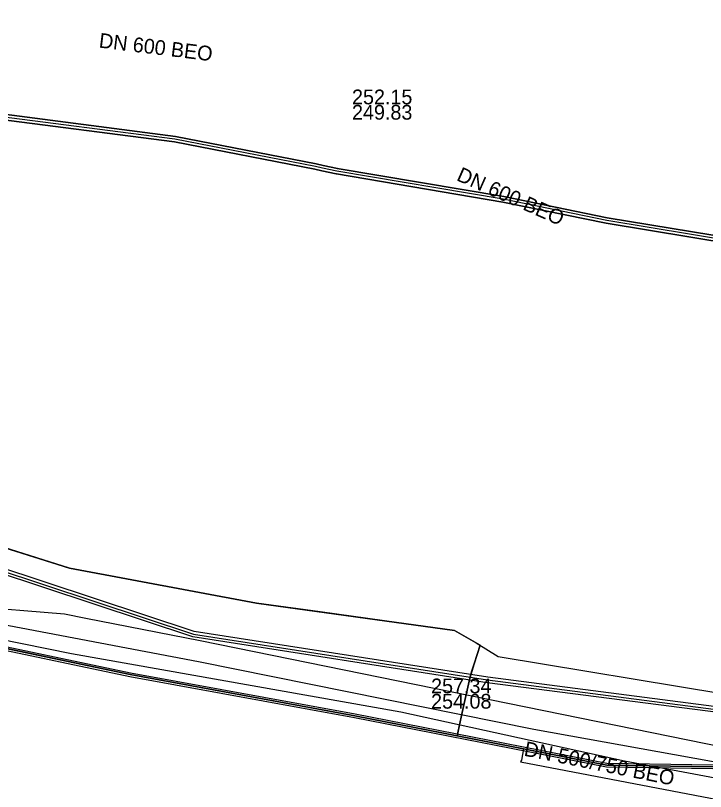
# Model space of a CAD drawing. Extents: x -599951 to -598963, y -1164095 to -1162939.
# Drawn here: x -599781.05 to -599743.65, y -1163060.04 to -1163017.95 of the extents above; entities that cross this region are included whole.
import ezdxf

# ---------------------------------------------------------------- set-up
doc = ezdxf.new("R2010")
doc.units = 0
for name, color, linetype in [('Vrstva 12', 7, 'Continuous'), ('Vrstva 20', 7, 'Continuous'), ('Vrstva 42', 7, 'Continuous'), ('Vrstva 44', 7, 'Continuous'), ('Vrstva 50', 7, 'Continuous'), ('Vrstva 55', 7, 'Continuous'), ('Vrstva 58', 7, 'Continuous')]:
    doc.layers.add(name, color=color, linetype=linetype)

msp = doc.modelspace()

# ---------------------------------------------------------------- linework, layer by layer
at = {"layer": 'Vrstva 12'}
for p, q in [((-599777.23, -1163050.66), (-599778.4, -1163050.43)), ((-599771.04, -1163051.87), (-599777.23, -1163050.66)), ((-599687.5, -1163068.9), (-599771.04, -1163051.87))]:
    msp.add_line(p, q, dxfattribs=at)
msp.add_lwpolyline([(-599778.4, -1163050.43), (-599783.7, -1163049.99), (-599784.71, -1163049.77)], dxfattribs=at)
at = {"layer": 'Vrstva 20'}
msp.add_lwpolyline([(-599883.05, -1163052.54), (-599873.56, -1163051.94), (-599873.14, -1163051.47), (-599872.98, -1163049.36), (-599872.6, -1163047.57), (-599869.57, -1163036.17), (-599869.08, -1163035.73), (-599867.99, -1163036.09), (-599863.42, -1163036.97), (-599853.5, -1163038.54), (-599849.37, -1163039.34), (-599847.49, -1163039.61), (-599846.18, -1163040.18), (-599841.31, -1163041.11), (-599828.6, -1163043.61), (-599815.43, -1163046.17), (-599809.1, -1163047.15), (-599803.22, -1163048.59), (-599792.42, -1163050.98), (-599783.94, -1163051.78), (-599774.84, -1163053.7), (-599762.66, -1163055.93), (-599749, -1163058.61), (-599740.93, -1163058.73)], dxfattribs=at)
at = {"layer": 'Vrstva 42'}
for p, q in [((-599783.799, -1163046.138), (-599778.116, -1163047.934)), ((-599783.799, -1163046.138), (-599778.116, -1163047.934)), ((-599778.116, -1163047.934), (-599767.984, -1163049.822)), ((-599778.116, -1163047.934), (-599767.984, -1163049.822)), ((-599767.984, -1163049.822), (-599757.25, -1163051.301)), ((-599767.984, -1163049.822), (-599757.25, -1163051.301)), ((-599757.25, -1163051.301), (-599756.084, -1163051.968)), ((-599757.25, -1163051.301), (-599756.084, -1163051.968)), ((-599756.084, -1163051.968), (-599754.889, -1163052.719)), ((-599756.084, -1163051.968), (-599754.889, -1163052.719)), ((-599754.889, -1163052.719), (-599742.1, -1163054.827)), ((-599754.889, -1163052.719), (-599742.1, -1163054.827))]:
    msp.add_line(p, q, dxfattribs=at)
for points in [[(-599735.209, -1163031.191), (-599748.973, -1163028.922), (-599754.582, -1163027.773), (-599763.609, -1163026.245), (-599763.605, -1163026.246), (-599764.382, -1163026.091), (-599764.757, -1163025.994), (-599772.386, -1163024.512), (-599782.512, -1163023.201), (-599802.063, -1163021.081), (-599815.518, -1163019.48), (-599820.791, -1163019.23), (-599821.01, -1163019.37), (-599822.87, -1163019.4), (-599823.02, -1163019.991), (-599823.159, -1163020.568)], [(-599735.209, -1163031.191), (-599748.973, -1163028.922), (-599754.582, -1163027.773), (-599763.609, -1163026.245), (-599763.605, -1163026.246), (-599764.382, -1163026.091), (-599764.757, -1163025.994), (-599772.386, -1163024.512), (-599782.512, -1163023.201), (-599802.063, -1163021.081), (-599815.518, -1163019.48), (-599820.791, -1163019.23), (-599821.01, -1163019.37), (-599822.87, -1163019.4), (-599823.02, -1163019.991), (-599823.159, -1163020.568)], [(-599823.02, -1163019.991), (-599822.87, -1163019.4), (-599821.01, -1163019.37), (-599820.791, -1163019.23), (-599815.518, -1163019.48), (-599802.063, -1163021.081), (-599782.512, -1163023.201), (-599772.386, -1163024.512), (-599764.757, -1163025.994), (-599764.382, -1163026.091), (-599763.605, -1163026.246), (-599763.609, -1163026.245), (-599754.582, -1163027.773), (-599748.973, -1163028.922), (-599735.209, -1163031.191)], [(-599823.02, -1163019.991), (-599822.87, -1163019.4), (-599821.01, -1163019.37), (-599820.791, -1163019.23), (-599815.518, -1163019.48), (-599802.063, -1163021.081), (-599782.512, -1163023.201), (-599772.386, -1163024.512), (-599764.757, -1163025.994), (-599764.382, -1163026.091), (-599763.605, -1163026.246), (-599763.609, -1163026.245), (-599754.582, -1163027.773), (-599748.973, -1163028.922), (-599735.209, -1163031.191)], [(-599735.209, -1163031.191), (-599748.973, -1163028.922), (-599754.582, -1163027.773), (-599763.609, -1163026.245), (-599763.605, -1163026.246), (-599764.382, -1163026.091), (-599764.757, -1163025.994), (-599772.386, -1163024.512), (-599782.512, -1163023.201), (-599802.063, -1163021.081), (-599815.518, -1163019.48), (-599820.791, -1163019.23), (-599821.01, -1163019.37), (-599822.87, -1163019.4), (-599823.02, -1163019.991)], [(-599823.02, -1163019.991), (-599822.87, -1163019.4), (-599821.01, -1163019.37), (-599820.791, -1163019.23), (-599815.518, -1163019.48), (-599802.063, -1163021.081), (-599782.512, -1163023.201), (-599772.386, -1163024.512), (-599764.757, -1163025.994), (-599764.382, -1163026.091), (-599763.605, -1163026.246), (-599763.609, -1163026.245), (-599754.582, -1163027.773), (-599748.973, -1163028.922), (-599735.209, -1163031.191)], [(-599763.634, -1163026.393), (-599764.416, -1163026.237), (-599764.79, -1163026.14), (-599772.41, -1163024.66), (-599782.53, -1163023.35), (-599802.08, -1163021.23), (-599815.53, -1163019.63), (-599821.01, -1163019.37)], [(-599735.209, -1163031.191), (-599748.973, -1163028.922), (-599754.582, -1163027.773), (-599763.609, -1163026.245), (-599763.605, -1163026.246), (-599764.382, -1163026.091), (-599764.757, -1163025.994), (-599772.386, -1163024.512), (-599782.512, -1163023.201), (-599802.063, -1163021.081), (-599815.518, -1163019.48)], [(-599735.209, -1163031.191), (-599748.973, -1163028.922), (-599754.582, -1163027.773), (-599763.609, -1163026.245), (-599763.605, -1163026.246), (-599764.382, -1163026.091), (-599764.757, -1163025.994), (-599772.386, -1163024.512), (-599782.512, -1163023.201), (-599802.063, -1163021.081), (-599815.518, -1163019.48)], [(-599735.259, -1163031.487), (-599749.027, -1163029.218), (-599754.638, -1163028.067), (-599763.659, -1163026.541), (-599763.663, -1163026.54), (-599764.45, -1163026.383), (-599764.823, -1163026.286), (-599772.434, -1163024.808), (-599782.548, -1163023.499), (-599802.097, -1163021.379), (-599815.542, -1163019.78), (-599820.691, -1163019.536), (-599820.864, -1163019.668), (-599822.636, -1163019.696), (-599822.861, -1163020.61), (-599823.009, -1163021.656), (-599827.686, -1163021.81)], [(-599735.259, -1163031.487), (-599749.027, -1163029.218), (-599754.638, -1163028.067), (-599763.659, -1163026.541), (-599763.663, -1163026.54), (-599764.45, -1163026.383), (-599764.823, -1163026.286), (-599772.434, -1163024.808), (-599782.548, -1163023.499), (-599802.097, -1163021.379), (-599815.542, -1163019.78), (-599820.691, -1163019.536), (-599820.864, -1163019.668), (-599822.636, -1163019.696), (-599822.861, -1163020.61), (-599823.009, -1163021.656), (-599827.686, -1163021.81)], [(-599820.866, -1163019.856), (-599820.864, -1163019.668), (-599820.691, -1163019.536), (-599815.542, -1163019.78), (-599802.097, -1163021.379), (-599782.548, -1163023.499), (-599772.434, -1163024.808), (-599764.823, -1163026.286), (-599764.45, -1163026.383), (-599763.663, -1163026.54), (-599763.659, -1163026.541), (-599754.638, -1163028.067), (-599749.027, -1163029.218), (-599735.259, -1163031.487)], [(-599820.866, -1163019.856), (-599820.864, -1163019.668), (-599820.691, -1163019.536), (-599815.542, -1163019.78), (-599802.097, -1163021.379), (-599782.548, -1163023.499), (-599772.434, -1163024.808), (-599764.823, -1163026.286), (-599764.45, -1163026.383), (-599763.663, -1163026.54), (-599763.659, -1163026.541), (-599754.638, -1163028.067), (-599749.027, -1163029.218), (-599735.259, -1163031.487)], [(-599614.55, -1163035.59), (-599618.49, -1163036.03), (-599632.12, -1163038.43), (-599646.48, -1163040.13), (-599659.15, -1163040.8), (-599677.55, -1163040.46), (-599690.39, -1163039.28), (-599700.24, -1163038.28), (-599705.3, -1163037.57), (-599712.89, -1163035.78), (-599723.95, -1163033.32), (-599735.234, -1163031.339), (-599749, -1163029.07), (-599754.61, -1163027.92), (-599763.634, -1163026.393)], [(-599742.215, -1163055.552), (-599755.449, -1163053.841), (-599771.375, -1163051.364), (-599782.13, -1163047.795), (-599795.02, -1163044.953), (-599808.565, -1163042.372), (-599820.407, -1163040.592), (-599840.692, -1163037.303), (-599847.928, -1163035.723), (-599848.08, -1163035.69), (-599848.987, -1163040.732), (-599851.308, -1163052.683), (-599851.739, -1163055.17), (-599852.233, -1163060.359), (-599893.313, -1163090.719), (-599898.373, -1163096.584), (-599905.793, -1163118.694), (-599909.483, -1163130.424), (-599919.431, -1163160.679), (-599923.942, -1163172.071), (-599928.754, -1163188.287), (-599951.125, -1163246.248)], [(-599742.215, -1163055.552), (-599755.449, -1163053.841), (-599771.375, -1163051.364), (-599782.13, -1163047.795), (-599795.02, -1163044.953), (-599808.565, -1163042.372), (-599820.407, -1163040.592), (-599840.692, -1163037.303), (-599847.928, -1163035.723), (-599848.08, -1163035.69), (-599848.987, -1163040.732), (-599851.308, -1163052.683), (-599851.739, -1163055.17), (-599852.233, -1163060.359), (-599893.313, -1163090.719), (-599898.373, -1163096.584), (-599905.793, -1163118.694), (-599909.483, -1163130.424), (-599919.431, -1163160.679), (-599923.942, -1163172.071), (-599928.754, -1163188.287), (-599951.125, -1163246.248)], [(-599847.96, -1163035.87), (-599840.72, -1163037.45), (-599820.43, -1163040.74), (-599808.59, -1163042.52), (-599795.05, -1163045.1), (-599782.17, -1163047.94), (-599771.41, -1163051.51), (-599755.47, -1163053.99), (-599742.24, -1163055.7), (-599730.83, -1163058.1), (-599723.97, -1163059.15), (-599715.25, -1163060.7), (-599698.74, -1163063.9), (-599666.16, -1163068.57), (-599655.17, -1163067.91), (-599647.96, -1163067.11), (-599641.24, -1163065.92), (-599633.17, -1163063.6), (-599622.92, -1163059.72), (-599616.64, -1163055.22), (-599609.94, -1163050.49)], [(-599742.265, -1163055.848), (-599755.491, -1163054.139), (-599771.445, -1163051.656), (-599782.21, -1163048.085), (-599795.08, -1163045.247), (-599808.615, -1163042.668), (-599820.453, -1163040.888), (-599840.748, -1163037.597), (-599847.84, -1163036.05), (-599848.693, -1163040.788), (-599851.012, -1163052.737), (-599851.441, -1163055.21), (-599851.947, -1163060.521), (-599893.107, -1163090.941), (-599898.107, -1163096.736), (-599905.507, -1163118.786), (-599909.197, -1163130.516), (-599919.149, -1163160.781), (-599923.658, -1163172.169), (-599928.466, -1163188.373), (-599951.125, -1163247.074)], [(-599742.265, -1163055.848), (-599755.491, -1163054.139), (-599771.445, -1163051.656), (-599782.21, -1163048.085), (-599795.08, -1163045.247), (-599808.615, -1163042.668), (-599820.453, -1163040.888), (-599840.748, -1163037.597), (-599847.84, -1163036.05), (-599848.693, -1163040.788), (-599851.012, -1163052.737), (-599851.441, -1163055.21), (-599851.947, -1163060.521), (-599893.107, -1163090.941), (-599898.107, -1163096.736), (-599905.507, -1163118.786), (-599909.197, -1163130.516), (-599919.149, -1163160.781), (-599923.658, -1163172.169), (-599928.466, -1163188.373), (-599951.125, -1163247.074)]]:
    msp.add_lwpolyline(points, dxfattribs=at)
at = {"layer": 'Vrstva 44'}
msp.add_lwpolyline([(-599951.125, -1163018.319), (-599947.551, -1163019.333), (-599942.738, -1163020.646), (-599932.806, -1163022.793), (-599910.515, -1163027.389), (-599898.233, -1163029.739), (-599885.727, -1163032.363), (-599873.009, -1163034.84), (-599861.264, -1163036.995), (-599853.19, -1163038.533), (-599847.084, -1163039.492), (-599839.909, -1163041.111), (-599824.895, -1163043.577), (-599814.349, -1163045.484), (-599801.363, -1163047.973), (-599790.063, -1163050.107), (-599778.01, -1163052.554), (-599760.155, -1163055.725), (-599748.035, -1163058.372), (-599724.432, -1163062.801)], dxfattribs=at)
at = {"layer": 'Vrstva 50'}
msp.add_lwpolyline([(-599740.93, -1163058.73), (-599749, -1163058.61), (-599762.66, -1163055.93), (-599774.84, -1163053.7), (-599782.792, -1163052.031), (-599783.94, -1163051.78), (-599792.42, -1163050.98), (-599803.22, -1163048.59), (-599809.1, -1163047.15), (-599809.988, -1163047.015), (-599815.43, -1163046.17), (-599843.958, -1163040.613)], dxfattribs=at)
at = {"layer": 'Vrstva 55'}
for points in [[(-599846.18, -1163040.18), (-599815.43, -1163046.17), (-599809.988, -1163047.015), (-599809.97, -1163047.41), (-599809.79, -1163047.045), (-599809.1, -1163047.15), (-599803.22, -1163048.59), (-599792.42, -1163050.98), (-599783.94, -1163051.78), (-599782.988, -1163051.989), (-599783.05, -1163052.73), (-599782.792, -1163052.031), (-599774.84, -1163053.7), (-599762.66, -1163055.93), (-599753.51, -1163057.73), (-599753.62, -1163058.34)], [(-599753.62, -1163058.34), (-599753.67, -1163058.437), (-599721.636, -1163064.562)]]:
    msp.add_lwpolyline(points, dxfattribs=at)
at = {"layer": 'Vrstva 58'}
for points in [[(-599951.125, -1163017.951), (-599942.396, -1163020.445), (-599928.216, -1163023.175), (-599909.436, -1163026.875), (-599898.216, -1163029.295), (-599876.466, -1163033.695), (-599839.596, -1163041.095), (-599823.356, -1163043.075), (-599809.226, -1163045.765), (-599771.136, -1163052.985), (-599752.946, -1163056.655), (-599739.506, -1163059.075)], [(-599951.125, -1163017.951), (-599942.396, -1163020.445), (-599928.216, -1163023.175), (-599909.436, -1163026.875), (-599898.216, -1163029.295), (-599876.466, -1163033.695), (-599839.596, -1163041.095), (-599823.356, -1163043.075), (-599809.226, -1163045.765), (-599771.136, -1163052.985), (-599752.946, -1163056.655), (-599739.506, -1163059.075)], [(-599895.104, -1163026.704), (-599877.002, -1163030.363), (-599865.209, -1163032.412), (-599856.59, -1163034.344), (-599852.059, -1163034.673), (-599843.593, -1163035.7), (-599839.077, -1163036.896), (-599826.206, -1163038.978), (-599807.734, -1163041.119), (-599798.148, -1163043.163), (-599783.799, -1163046.138), (-599778.116, -1163047.934), (-599767.984, -1163049.822), (-599757.25, -1163051.301), (-599755.861, -1163052.095), (-599756.19, -1163053.12), (-599756.43, -1163053.89), (-599756.84, -1163055.76), (-599757.116, -1163057.018), (-599762.66, -1163055.93)], [(-599895.104, -1163026.704), (-599877.002, -1163030.363), (-599865.209, -1163032.412), (-599856.59, -1163034.344), (-599852.059, -1163034.673), (-599843.593, -1163035.7), (-599839.077, -1163036.896), (-599826.206, -1163038.978), (-599807.734, -1163041.119), (-599798.148, -1163043.163), (-599783.799, -1163046.138), (-599778.116, -1163047.934), (-599767.984, -1163049.822), (-599757.25, -1163051.301), (-599755.861, -1163052.095), (-599756.19, -1163053.12), (-599756.43, -1163053.89), (-599756.84, -1163055.76), (-599757.116, -1163057.018), (-599762.66, -1163055.93)], [(-599895.104, -1163026.704), (-599877.002, -1163030.363), (-599865.209, -1163032.412), (-599856.59, -1163034.344), (-599852.059, -1163034.673), (-599843.593, -1163035.7), (-599839.077, -1163036.896), (-599826.206, -1163038.978), (-599807.734, -1163041.119), (-599798.148, -1163043.163), (-599783.799, -1163046.138), (-599778.116, -1163047.934), (-599767.984, -1163049.822), (-599757.25, -1163051.301), (-599755.861, -1163052.095), (-599756.19, -1163053.12), (-599756.43, -1163053.89), (-599756.84, -1163055.76), (-599757.116, -1163057.018), (-599762.66, -1163055.93)], [(-599869.54, -1163034.95), (-599867.965, -1163035.993), (-599863.403, -1163036.871), (-599853.483, -1163038.441), (-599849.353, -1163039.241), (-599847.462, -1163039.513), (-599846.15, -1163040.084), (-599841.291, -1163041.012), (-599828.581, -1163043.512), (-599815.413, -1163046.071), (-599809.08, -1163047.052), (-599803.197, -1163048.493), (-599792.404, -1163050.881), (-599783.925, -1163051.681), (-599774.821, -1163053.602), (-599762.641, -1163055.832), (-599748.99, -1163058.51), (-599740.918, -1163058.63)], [(-599762.66, -1163055.93), (-599772.176, -1163054.188), (-599774.84, -1163053.7), (-599783.94, -1163051.78), (-599792.42, -1163050.98), (-599803.22, -1163048.59), (-599809.1, -1163047.15), (-599809.988, -1163047.015), (-599815.43, -1163046.17), (-599843.958, -1163040.613), (-599846.18, -1163040.18), (-599847.49, -1163039.61), (-599849.37, -1163039.34), (-599854.299, -1163038.414), (-599863.42, -1163036.97), (-599867.99, -1163036.09), (-599869.08, -1163035.73), (-599869.57, -1163036.17), (-599872.613, -1163047.558), (-599872.98, -1163049.36), (-599873.14, -1163051.47), (-599873.56, -1163051.94), (-599883.05, -1163052.54)], [(-599762.66, -1163055.93), (-599772.176, -1163054.188), (-599774.84, -1163053.7), (-599783.94, -1163051.78), (-599792.42, -1163050.98), (-599803.22, -1163048.59), (-599809.1, -1163047.15), (-599809.988, -1163047.015), (-599815.43, -1163046.17), (-599843.958, -1163040.613), (-599846.18, -1163040.18), (-599847.49, -1163039.61), (-599849.37, -1163039.34), (-599854.299, -1163038.414), (-599863.42, -1163036.97), (-599867.99, -1163036.09), (-599869.08, -1163035.73), (-599869.57, -1163036.17), (-599872.613, -1163047.558), (-599872.98, -1163049.36), (-599873.14, -1163051.47), (-599873.56, -1163051.94), (-599883.05, -1163052.54)], [(-599762.66, -1163055.93), (-599772.176, -1163054.188), (-599774.84, -1163053.7), (-599783.94, -1163051.78), (-599792.42, -1163050.98), (-599803.22, -1163048.59), (-599809.1, -1163047.15), (-599809.988, -1163047.015), (-599815.43, -1163046.17), (-599843.958, -1163040.613), (-599846.18, -1163040.18), (-599847.49, -1163039.61), (-599849.37, -1163039.34), (-599854.299, -1163038.414), (-599863.42, -1163036.97), (-599867.99, -1163036.09), (-599869.08, -1163035.73), (-599869.57, -1163036.17), (-599872.613, -1163047.558), (-599872.98, -1163049.36), (-599873.14, -1163051.47), (-599873.56, -1163051.94), (-599883.05, -1163052.54)], [(-599843.958, -1163040.613), (-599815.43, -1163046.17), (-599809.988, -1163047.015), (-599809.1, -1163047.15), (-599803.22, -1163048.59), (-599792.42, -1163050.98), (-599783.94, -1163051.78), (-599774.84, -1163053.7), (-599772.176, -1163054.188), (-599762.66, -1163055.93), (-599757.116, -1163057.018), (-599756.84, -1163055.76), (-599756.43, -1163053.89), (-599756.19, -1163053.12), (-599755.861, -1163052.095), (-599757.25, -1163051.301), (-599767.984, -1163049.822), (-599778.116, -1163047.934), (-599783.799, -1163046.138), (-599798.148, -1163043.163), (-599807.734, -1163041.119), (-599826.206, -1163038.978)], [(-599843.958, -1163040.613), (-599815.43, -1163046.17), (-599809.988, -1163047.015), (-599809.1, -1163047.15), (-599803.22, -1163048.59), (-599792.42, -1163050.98), (-599783.94, -1163051.78), (-599774.84, -1163053.7), (-599772.176, -1163054.188), (-599762.66, -1163055.93), (-599757.116, -1163057.018), (-599756.84, -1163055.76), (-599756.43, -1163053.89), (-599756.19, -1163053.12), (-599755.861, -1163052.095), (-599757.25, -1163051.301), (-599767.984, -1163049.822), (-599778.116, -1163047.934), (-599783.799, -1163046.138), (-599798.148, -1163043.163), (-599807.734, -1163041.119), (-599826.206, -1163038.978)], [(-599843.958, -1163040.613), (-599815.43, -1163046.17), (-599809.988, -1163047.015), (-599809.1, -1163047.15), (-599803.22, -1163048.59), (-599792.42, -1163050.98), (-599783.94, -1163051.78), (-599774.84, -1163053.7), (-599772.176, -1163054.188), (-599762.66, -1163055.93), (-599757.116, -1163057.018), (-599756.84, -1163055.76), (-599756.43, -1163053.89), (-599756.19, -1163053.12), (-599755.861, -1163052.095), (-599757.25, -1163051.301), (-599767.984, -1163049.822), (-599778.116, -1163047.934), (-599783.799, -1163046.138), (-599798.148, -1163043.163), (-599807.734, -1163041.119), (-599826.206, -1163038.978)], [(-599740.93, -1163058.73), (-599749, -1163058.61), (-599757.116, -1163057.018), (-599756.84, -1163055.76), (-599756.43, -1163053.89), (-599756.307, -1163053.495), (-599756.188, -1163053.113), (-599755.861, -1163052.095), (-599757.25, -1163051.301), (-599759.361, -1163051.01), (-599764.528, -1163050.298), (-599767.984, -1163049.822), (-599778.116, -1163047.934), (-599779.105, -1163047.622), (-599783.799, -1163046.138), (-599798.148, -1163043.163), (-599798.593, -1163043.068), (-599803.287, -1163042.067), (-599807.734, -1163041.119), (-599826.206, -1163038.978)], [(-599783.955, -1163051.879), (-599774.859, -1163053.798), (-599762.679, -1163056.028), (-599749.01, -1163058.71), (-599740.942, -1163058.83)], [(-599783.955, -1163051.879), (-599774.859, -1163053.798), (-599762.679, -1163056.028), (-599749.01, -1163058.71), (-599740.942, -1163058.83)]]:
    msp.add_lwpolyline(points, dxfattribs=at)

# ---------------------------------------------------------------- texts
at = {"layer": 'Vrstva 12'}
for s, rotation, p in [('DN 600 BEO', 353.049, (-599776.559, -1163019.685)), ('DN 600 BEO', 336.2116, (-599757.193, -1163026.873)), ('DN 500/750 BEO', 348.6295, (-599753.528, -1163058.092))]:
    msp.add_text(s, height=0.8, rotation=rotation, dxfattribs=at).set_placement(p)
for s, p in [('252.15', (-599762.81, -1163022.767)), ('249.83', (-599762.81, -1163023.599)), ('257.34', (-599758.524, -1163054.714)), ('254.08', (-599758.524, -1163055.546))]:
    msp.add_text(s, height=0.8, dxfattribs=at).set_placement(p)

doc.saveas('drawing.dxf')
